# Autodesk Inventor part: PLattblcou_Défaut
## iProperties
Shininess: 64.0
Length Units: 11269
Angle Units: 11279
Time Units: 11290
Mass Units: 11283
Length Display Precision: 3
Angle Display Precision: 2
Compacted: True
Part Number: PLattblcou_Défaut
Document SubType Name: Modeling
Created: 2006-11
Material: Par défaut
Designer: profs_sti
Density: 0.0
Volumn: 0.0
Area: 0.0
PropertySet Name: Model Information
Control State: 0
Master: False
Checked Out: False
Author: profs_sti
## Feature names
1. Base1
